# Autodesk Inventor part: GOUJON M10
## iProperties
Created: 2004-11
Part Number: GOUJON M10
Document SubType Name: Modeling
Designer: Bruno
Manufacturer: Standard
Standards Organization: Custom
Author: Bruno
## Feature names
1. Base1
